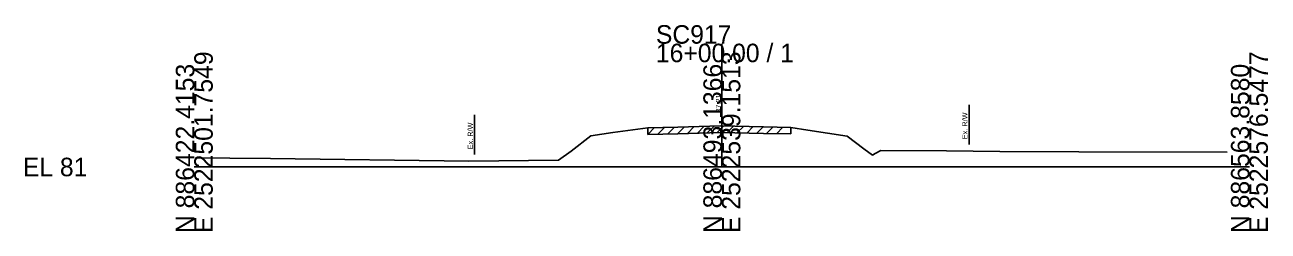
# Model space of a CAD drawing. Extents: x -26 to 218, y -10 to 12021.
# Drawn here: x -25.7 to 162.8, y 11990.3 to 12021.5 of the extents above; entities that cross this region are included whole.
import ezdxf

# ---------------------------------------------------------------- set-up
doc = ezdxf.new("R2010")
doc.units = 0
for name, color, linetype in [('RD_GPK_XS_Cell', 7, 'Continuous'), ('RD_XS_ExGround', 7, 'Continuous'), ('RD_XS_ExPaveRet', 7, 'Continuous'), ('RD_XS_ExRW', 7, 'Continuous'), ('RD_XS_TX_Elev_EX', 7, 'Continuous')]:
    doc.layers.add(name, color=color, linetype=linetype)

msp = doc.modelspace()

# ---------------------------------------------------------------- linework, layer by layer
at = {"layer": 'RD_GPK_XS_Cell'}
for p, q in [((80, 12000), (80, 12018.65)), ((0, 12000), (80, 12000)), ((80, 12000), (160, 12000))]:
    msp.add_line(p, q, dxfattribs=at)
at = {"layer": 'RD_XS_ExGround'}
for p, q in [((63.48, 12005.2), (68.79, 12005.93)), ((68.79, 12005.93), (73.33, 12006.04)), ((73.33, 12006.04), (79.82, 12006.22)), ((79.82, 12006.22), (86.32, 12006.08)), ((86.32, 12006.08), (90.45, 12005.99)), ((90.45, 12005.99), (93.02, 12005.57)), ((57.13, 12002.4), (60.11, 12004.72)), ((60.11, 12004.72), (63.48, 12005.2)), ((93.02, 12005.57), (99.02, 12004.64)), ((99.02, 12004.64), (101.54, 12002.75)), ((55.25, 12001.02), (57.13, 12002.4)), ((101.54, 12002.75), (102.82, 12001.8)), ((102.82, 12001.8), (103.24, 12002.02)), ((103.24, 12002.02), (104.1, 12002.49)), ((104.1, 12002.49), (114.07, 12002.45)), ((114.07, 12002.45), (122.17, 12002.36)), ((122.17, 12002.36), (134.14, 12002.28)), ((134.14, 12002.28), (156.65, 12002.25)), ((0.39, 12001.36), (5.39, 12001.34)), ((5.39, 12001.34), (11.55, 12001.3)), ((11.55, 12001.3), (41.64, 12000.87)), ((41.64, 12000.87), (55.25, 12001.02))]:
    msp.add_line(p, q, dxfattribs=at)
at = {"layer": 'RD_XS_ExPaveRet'}
for p, q in [((68.79, 12004.93), (69.81, 12005.96)), ((68.79, 12004.93), (68.79, 12005.93)), ((70.29, 12004.97), (71.31, 12005.99)), ((71.79, 12005), (72.81, 12006.03)), ((73.29, 12005.04), (74.32, 12006.07)), ((74.79, 12005.08), (75.82, 12006.11)), ((76.29, 12005.12), (77.32, 12006.15)), ((77.79, 12005.16), (78.82, 12006.19)), ((79.29, 12005.2), (80.29, 12006.21)), ((80.79, 12005.2), (81.77, 12006.18)), ((82.29, 12005.16), (83.27, 12006.14)), ((83.79, 12005.13), (84.77, 12006.11)), ((85.29, 12005.1), (86.27, 12006.08)), ((86.79, 12005.07), (87.77, 12006.05)), ((88.29, 12005.04), (89.27, 12006.02)), ((90.45, 12005.99), (90.45, 12004.99)), ((68.79, 12004.93), (73.33, 12005.04)), ((73.33, 12005.04), (79.82, 12005.22)), ((79.82, 12005.22), (86.32, 12005.08)), ((86.32, 12005.08), (90.45, 12004.99))]:
    msp.add_line(p, q, dxfattribs=at)
at = {"layer": 'RD_XS_ExRW'}
for p, q in [((42.5, 12007.88), (42.5, 12001.88)), ((117.5, 12009.41), (117.5, 12003.41)), ((117.5, 12009.41), (117.5, 12003.41))]:
    msp.add_line(p, q, dxfattribs=at)

# ---------------------------------------------------------------- texts
at = {"layer": 'RD_GPK_XS_Cell'}
for s, p in [('SC917', (70, 12018.65)), ('16+00.00 / 1', (70, 12015.85)), ('EL 81', (-26, 11998.6))]:
    msp.add_text(s, height=2.8, dxfattribs=at).set_placement(p)
for s, p in [('E 2522501.7549', (2.8, 11990)), ('E 2522539.1513', (82.8, 11990)), ('E 2522576.5477', (162.8, 11990)), ('N 886422.4153', (0, 11990)), ('N 886493.1366', (80, 11990)), ('N 886563.8580', (160, 11990))]:
    msp.add_text(s, height=2.8, rotation=90, dxfattribs=at).set_placement(p)
at = {"layer": 'RD_XS_ExRW'}
for p in [(117.25, 12004.2), (117.25, 12004.2), (42.25, 12002.67)]:
    msp.add_text('Ex. R/W ', height=0.8, rotation=90, dxfattribs=at).set_placement(p)
at = {"layer": 'RD_XS_TX_Elev_EX'}
msp.add_text('87.21', height=0.8, rotation=90, dxfattribs=at).set_placement((79.9, 12008.21))

doc.saveas('drawing.dxf')
